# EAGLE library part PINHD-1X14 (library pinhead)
PIN HEADER
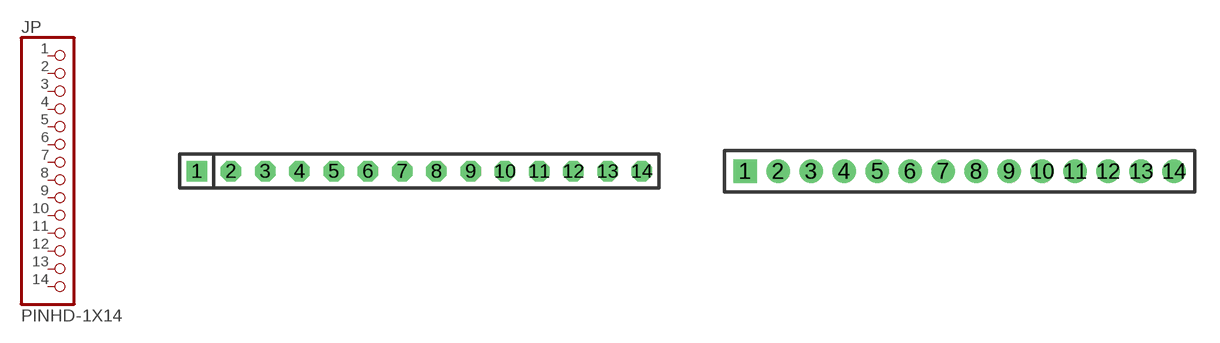
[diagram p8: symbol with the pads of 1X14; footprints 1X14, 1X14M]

Designator prefix JP

## PINHD-1X14  [1X14]
1  1  pas
2  2  pas
3  3  pas
4  4  pas
5  5  pas
6  6  pas
7  7  pas
8  8  pas
9  9  pas
10  10  pas
11  11  pas
12  12  pas
13  13  pas
14  14  pas

## PINHD-1X14M  [1X14M]
Pads as for 1X14

## Footprint 1X14 (pad centres in mm)
PIN HEADER - 0.1"
drill 1.016 square: 1 -16.51,0
drill 1.016 octagon: 2 -13.97,0; 3 -11.43,0; 4 -8.89,0; 5 -6.35,0; 6 -3.81,0; 7 -1.27,0; 8 1.27,0; 9 3.81,0; 10 6.35,0; 11 8.89,0; 12 11.43,0; 13 13.97,0; 14 16.51,0

## Footprint 1X14M (pad centres in mm)
PIN HEADER - 2MM"
drill 0.914 square: 1 -13,0
drill 0.914 round: 2 -11,0; 3 -9,0; 4 -7,0; 5 -5,0; 6 -3,0; 7 -1,0; 8 1,0; 9 3,0; 10 5,0; 11 7,0; 12 9,0; 13 11,0; 14 13,0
